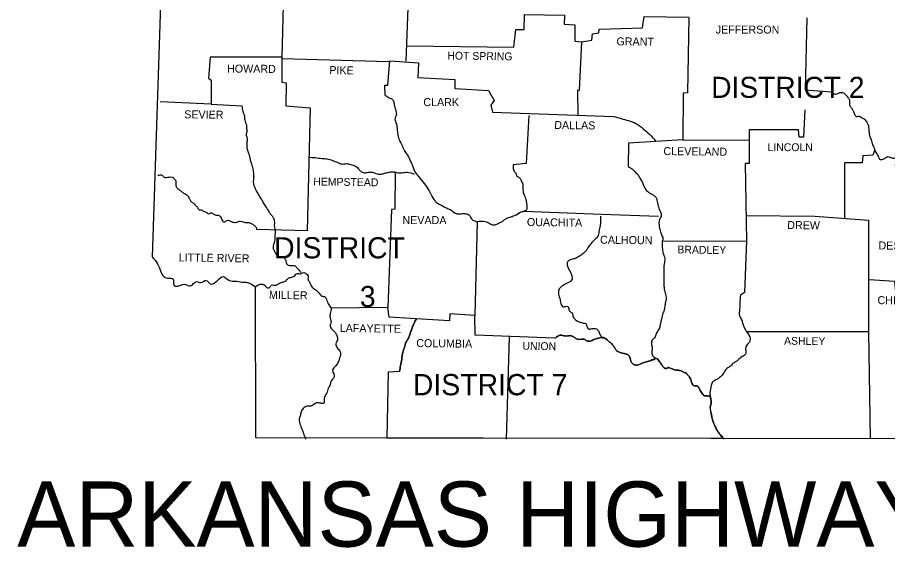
# Model space of a CAD drawing. Extents: x 185 to 5012, y 113 to 2127.
# Drawn here: x 4271.6 to 4728.7, y 1375.6 to 1654.2 of the extents above; entities that cross this region are included whole.
import ezdxf

# ---------------------------------------------------------------- set-up
doc = ezdxf.new("R2010")
doc.units = 0
for name, color, linetype in [('1', 7, 'Continuous'), ('2', 7, 'Continuous'), ('3', 7, 'Continuous'), ('S_MISC_BOUNDARY', 7, 'Continuous')]:
    doc.layers.add(name, color=color, linetype=linetype)

msp = doc.modelspace()

# ---------------------------------------------------------------- linework, layer by layer
at = {"layer": '1'}
for points in [[(4330.91, 1956.42), (4351.16, 1793.81), (4342.35, 1528.37)], [(4477.96, 1692.15), (4475.71, 1631.2)], [(4411.63, 1681.39), (4410.55, 1633.25), (4372.88, 1633.35), (4372, 1622.19), (4373.37, 1621.22), (4373.27, 1608.69), (4346.56, 1609.87)], [(4476.4, 1639.32), (4532.36, 1638.53), (4533.44, 1647.83), (4537.84, 1647.83), (4537.94, 1655.66), (4559.07, 1655.36), (4558.88, 1650.67), (4564.35, 1650.27), (4564.35, 1641.66), (4567.88, 1641.37)], [(4567.88, 1641.37), (4573.36, 1642.15), (4573.75, 1645.48), (4576.98, 1646.07), (4577.17, 1648.02), (4599.97, 1648.71), (4600.85, 1654.68), (4624.23, 1654.29)], [(4624.23, 1654.09), (4623.65, 1614.56), (4621.4, 1614.47), (4621.1, 1589.91)], [(4686.26, 1653.99), (4685.48, 1616.13), (4699.08, 1615.05)], [(4567.88, 1641.37), (4566.7, 1615.74), (4565.82, 1616.03), (4565.92, 1602.72)], [(4410.55, 1633.25), (4410.55, 1620.24), (4412.7, 1619.85), (4412.51, 1607.71), (4425.42, 1606.74), (4423.86, 1542.06), (4397.24, 1542.75)], [(4410.74, 1632.57), (4466.71, 1631.1)], [(4464.85, 1613.19), (4464.66, 1618.57), (4466.22, 1618.67), (4467.2, 1631.29), (4482.27, 1630.32), (4481.88, 1622.59), (4501.35, 1621.51), (4501.44, 1616.81), (4519.05, 1615.74), (4522.09, 1610.45), (4520.23, 1608.11), (4521.11, 1604.49), (4584.9, 1602.14)], [(4373.27, 1608.69), (4389.51, 1607.71)], [(4685.19, 1605.66), (4684.6, 1591.28), (4682.35, 1591.28), (4681.96, 1595.09), (4655.93, 1595.09), (4655.93, 1589.61)], [(4540.29, 1602.63), (4538.82, 1577.48), (4532.07, 1576.7)], [(4607.01, 1589.03), (4592.53, 1588.15), (4592.44, 1575.92)], [(4621.1, 1589.91), (4606.82, 1589.03)], [(4621.1, 1589.91), (4655.74, 1589.71)], [(4655.93, 1589.71), (4656.03, 1577.48), (4653.98, 1577.38), (4654.56, 1536.78)], [(4722.07, 1584.53), (4720.9, 1581.88), (4715.71, 1581.4), (4715.42, 1577.87), (4706.13, 1577.87), (4706.03, 1548.62)], [(4470.04, 1572.98), (4469.84, 1553.51), (4468.08, 1553.31), (4466.12, 1501.75)], [(4537.84, 1552.34), (4578.35, 1550.87), (4608.38, 1549.69)], [(4654.27, 1550.09), (4690.57, 1549.79), (4718.75, 1547.64)], [(4513.18, 1546.86), (4511.91, 1497.55), (4498.7, 1498.43), (4498.61, 1494.81), (4480.99, 1495.88)], [(4718.75, 1547.64), (4718.75, 1489.13), (4719.53, 1432.87)], [(4610.34, 1536.68), (4654.56, 1536.78)], [(4654.56, 1536.78), (4653.59, 1509.58), (4651.43, 1508.21)], [(4719.24, 1516.43), (4732.35, 1515.65), (4732.93, 1509.97), (4744.77, 1510.36), (4745.26, 1515.16), (4747.51, 1515.16)], [(4396.46, 1512.61), (4396.66, 1433.46), (4755.24, 1432.87)], [(4480.99, 1495.88), (4466.81, 1496.67), (4466.12, 1501.75), (4436.48, 1501.46)], [(4553.89, 1485.61), (4512.11, 1487.17), (4511.91, 1497.06)], [(4529.91, 1486.29), (4528.35, 1432.58)], [(4655.15, 1489.23), (4718.75, 1489.23)], [(4472.38, 1468.19), (4466.32, 1467.8), (4465.63, 1433.36)]]:
    msp.add_lwpolyline(points, dxfattribs=at)
for points in [[(4699.08, 1615.05), (4700.55, 1614.07), (4702.6, 1614.17), (4703.97, 1614.76), (4705.05, 1614.66), (4706.52, 1613.78), (4707.5, 1612.61), (4708.18, 1611.73), (4708.67, 1610.36), (4708.67, 1609.08), (4709.16, 1607.32), (4709.75, 1606.64), (4710.53, 1605.37), (4711.02, 1604.19), (4711.31, 1603.41), (4712.39, 1602.14), (4713.37, 1602.24), (4714.25, 1602.14), (4715.42, 1601.45), (4717.18, 1600.08), (4717.48, 1599.69), (4718.65, 1597.15), (4718.85, 1595.58), (4719.04, 1593.53), (4719.43, 1591.57), (4720.22, 1589.42), (4720.61, 1587.95), (4721.49, 1585.9), (4722.07, 1584.53), (4722.86, 1582.76), (4724.03, 1580.81), (4724.52, 1579.63), (4726.18, 1579.73), (4727.36, 1580.22), (4728.24, 1581), (4729.31, 1580.91), (4730.49, 1580.51), (4732.05, 1580.22), (4733.03, 1580.81), (4733.52, 1581.2), (4733.62, 1582.08), (4734.5, 1582.57), (4735.48, 1581.88), (4736.55, 1580.32), (4736.55, 1579.34), (4736.16, 1578.75), (4734.89, 1577.97), (4733.13, 1577.38), (4732.64, 1576.7), (4734.3, 1575.92), (4736.95, 1575.72), (4737.63, 1576.31), (4739.39, 1575.82), (4740.08, 1576.31), (4742.42, 1576.21), (4743.5, 1576.99), (4745.65, 1576.89), (4746.34, 1576.41), (4746.34, 1575.52), (4748.1, 1575.13), (4749.37, 1575.43), (4751.03, 1574.94), (4752.5, 1574.15), (4753.29, 1573.08), (4754.26, 1571.9), (4755.14, 1572.2), (4755.83, 1573.08), (4757.3, 1574.64), (4757.3, 1575.62), (4757.69, 1576.31), (4758.18, 1577.29)], [(4464.85, 1613.19), (4466.42, 1612.21), (4468.28, 1611.33), (4469.25, 1609.87), (4469.65, 1607.62), (4470.33, 1605.17), (4470.53, 1602.63), (4469.94, 1601.26), (4470.72, 1598.13), (4471.01, 1595.97), (4471.31, 1593.43), (4472.09, 1590.01), (4473.36, 1587.66), (4474.54, 1584.82), (4476.49, 1581.79), (4478.16, 1578.46), (4478.94, 1576.7), (4480.41, 1573.08), (4482.27, 1570.63), (4485.2, 1566.91), (4487.84, 1563.1), (4489.31, 1560.26), (4491.56, 1557.13), (4494.11, 1555.57), (4497.33, 1553.9), (4499.39, 1552.92), (4501.74, 1551.26), (4504.77, 1551.06), (4507.02, 1551.06), (4509.07, 1550.18), (4510.05, 1548.42), (4511.81, 1547.25), (4513.18, 1546.86)], [(4389.51, 1607.71), (4390, 1604.78), (4390.88, 1602.24), (4390.98, 1600.28), (4391.86, 1597.34), (4391.86, 1596.27), (4392.16, 1594.11), (4391.76, 1592.94), (4392.25, 1590.59), (4392.16, 1588.83), (4392.16, 1587.36), (4392.25, 1584.92), (4393.04, 1582.76), (4393.82, 1579.54), (4394.31, 1577.87), (4395.09, 1575.33), (4395.58, 1572.2), (4395.68, 1569.85), (4395.48, 1567.7), (4396.07, 1565.25), (4397.15, 1562.81), (4398.51, 1560.46), (4400.18, 1557.82), (4401.35, 1555.76), (4402.82, 1553.51), (4403.99, 1551.65), (4405.76, 1549.3), (4406.54, 1547.35), (4406.54, 1544.61), (4406.93, 1542.06), (4406.83, 1539.23), (4406.64, 1536.68), (4405.95, 1533.16), (4406.44, 1531.5), (4408.3, 1529.05), (4409.47, 1528.37), (4411.53, 1527.97), (4412.51, 1526.6), (4413.09, 1524.55), (4415.15, 1523.86), (4417.4, 1523.67), (4418.47, 1522.49), (4419.94, 1520.93), (4420.43, 1520.15)], [(4584.9, 1602.14), (4592.53, 1599.98), (4596.45, 1598.52), (4600.36, 1595.68), (4603.59, 1592.84), (4606.82, 1589.22)], [(4425.23, 1580.71), (4428.94, 1580.42), (4432.37, 1580.03), (4435.01, 1579.73), (4437.75, 1578.75), (4440.2, 1577.87), (4441.76, 1577.19), (4444.4, 1577.38), (4446.65, 1576.89), (4449.2, 1576.01), (4451.06, 1574.35), (4452.23, 1573.08), (4454.48, 1572.59), (4456.34, 1572.88), (4458.59, 1572.69), (4461.13, 1571.9), (4463.19, 1572), (4464.85, 1572.39), (4466.81, 1572.88), (4469.25, 1573.08), (4471.11, 1572.69), (4473.56, 1572.59), (4476.4, 1572.88), (4479.92, 1571.9)], [(4532.07, 1576.7), (4532.07, 1574.84), (4532.75, 1573.08), (4533.44, 1572.3), (4533.73, 1571.02), (4534.61, 1570.44), (4535.88, 1569.26), (4536.57, 1567.6), (4537.06, 1566.52), (4537.06, 1565.15), (4537.16, 1563.78), (4537.35, 1562.12), (4538.52, 1559.19), (4538.82, 1558.01), (4539.01, 1557.03), (4539.11, 1555.37), (4539.11, 1553.41), (4537.84, 1552.34)], [(4592.44, 1575.92), (4594.69, 1574.45), (4596.54, 1572.49), (4597.91, 1571.02), (4598.79, 1569.36), (4599.97, 1567.4), (4601.63, 1563.69), (4603.1, 1562.41), (4605.15, 1561.14), (4606.43, 1560.26), (4607.7, 1557.42), (4608.29, 1554.59), (4609.36, 1552.04), (4609.85, 1550.09), (4608.97, 1548.13), (4608.77, 1544.22), (4609.36, 1541.57), (4610.14, 1539.62), (4610.63, 1537.37), (4610.34, 1536.68)], [(4345.39, 1571.22), (4347.54, 1571.32), (4349.01, 1570.05), (4349.89, 1570.14), (4351.45, 1570.34), (4352.92, 1570.24), (4354, 1569.36), (4354.88, 1567.8), (4354.78, 1566.33), (4354.88, 1565.74), (4355.56, 1564.47), (4356.74, 1563.49), (4358.01, 1562.51), (4359.18, 1561.73), (4361.14, 1560.46), (4361.34, 1560.07), (4362.12, 1558.5), (4363.1, 1557.23), (4364.27, 1556.45), (4365.54, 1555.08), (4366.13, 1554.49), (4367.11, 1553.12), (4368.18, 1553.02), (4369.65, 1552.14), (4370.73, 1551.85), (4371.9, 1551.06), (4373.08, 1551.46), (4374.54, 1550.87), (4376.5, 1550.28), (4377.58, 1550.09), (4378.85, 1548.23), (4380.12, 1546.66), (4381.69, 1547.54), (4384.62, 1546.66), (4386.48, 1546.56), (4388.14, 1547.05), (4389.42, 1546.96), (4391.76, 1546.37), (4393.23, 1546.37), (4394.8, 1545.78), (4396.26, 1544.61), (4397.24, 1543.34), (4397.24, 1542.75)], [(4535.98, 1551.95), (4533.44, 1550.28), (4531.48, 1549.5), (4530.01, 1549.01), (4528.64, 1548.62), (4526.88, 1547.44), (4525.51, 1546.47), (4523.65, 1545.59), (4521.89, 1545), (4519.74, 1545.68), (4518.57, 1546.37), (4517.29, 1546.86), (4513.18, 1546.86)], [(4533.44, 1550.28), (4535.98, 1551.95), (4537.84, 1552.34)], [(4577.95, 1549.69), (4577.76, 1544.8), (4577.07, 1541.77), (4576.39, 1539.03), (4574.92, 1537.46), (4573.36, 1535.9), (4571.89, 1534.14), (4570.62, 1531.99), (4569.34, 1530.62), (4567.68, 1529.25), (4566.02, 1528.27), (4564.16, 1527.39), (4562.1, 1526.9), (4560.64, 1525.82), (4560.54, 1523.47), (4562.2, 1520.15), (4562.79, 1518.58), (4562.99, 1516.72), (4562.3, 1515.65), (4560.73, 1514.77), (4558.88, 1513.69), (4557.21, 1512.71), (4556.04, 1511.05), (4555.84, 1508.8), (4556.63, 1506.16), (4556.92, 1504.59), (4558.19, 1502.14), (4559.17, 1502.24), (4560.93, 1502.14), (4561.13, 1501.65), (4561.22, 1501.17), (4561.62, 1499.89), (4563.08, 1498.82), (4563.28, 1497.84), (4564.16, 1495.98), (4565.63, 1494.71), (4566.7, 1494.32), (4568.95, 1493.63), (4570.13, 1493.34), (4571.4, 1490.5), (4572.96, 1490.6), (4574.14, 1490.79), (4576.1, 1490.31), (4576.98, 1489.13), (4577.86, 1487.17), (4579.03, 1485.8), (4579.81, 1485.8)], [(4610.34, 1536.68), (4610.73, 1530.62), (4611.61, 1527.68), (4611.32, 1524.55), (4611.22, 1521.52), (4611.22, 1518.78), (4611.22, 1516.14), (4611.22, 1513.4), (4611.42, 1511.44), (4612.1, 1508.6), (4612.39, 1505.96), (4611.81, 1503.42), (4611.51, 1501.07), (4610.73, 1498.72), (4610.05, 1496.08), (4609.26, 1492.65), (4608.58, 1490.4), (4607.21, 1488.06), (4606.33, 1485.9), (4604.96, 1484.53), (4604.76, 1482.18), (4605.06, 1480.03), (4604.86, 1478.08), (4605.55, 1476.22), (4607.31, 1474.94)], [(4342.35, 1528.37), (4345.19, 1524.65), (4346.37, 1522.01), (4348.03, 1518.58), (4350.48, 1517.21), (4353.31, 1516.72), (4353.9, 1513.4), (4356.83, 1513.3), (4359.18, 1513.98), (4362.41, 1513.1), (4365.84, 1515.45), (4367.79, 1514.86), (4370.63, 1516.04), (4372.78, 1514.28), (4376.5, 1515.84), (4379.83, 1517.99), (4382.96, 1515.94), (4385.99, 1515.65), (4389.61, 1515.16), (4392.45, 1514.96), (4394.99, 1513.69), (4396.85, 1512.42), (4396.46, 1512.61)], [(4396.46, 1512.61), (4399.88, 1514.08), (4401.35, 1513.59), (4402.62, 1512.32), (4404.09, 1512.32), (4404.87, 1513.49), (4406.34, 1513.59), (4407.52, 1513.49), (4408.79, 1514.28), (4409.86, 1514.77), (4411.33, 1515.25), (4412.41, 1515.65), (4413.39, 1516.72), (4415.15, 1517.6), (4417.2, 1518.29), (4417.79, 1519.27), (4418.77, 1519.66), (4420.72, 1519.56), (4422, 1520.15), (4423.07, 1519.66), (4424.05, 1518.97), (4424.25, 1516.43), (4425.03, 1515.06), (4426.2, 1512.61), (4427.87, 1511.34), (4429.43, 1510.07), (4430.02, 1509.29), (4431.68, 1507.82), (4433.15, 1507.33), (4433.84, 1506.25), (4434.91, 1503.71), (4436.48, 1501.46)], [(4651.43, 1508.21), (4651.14, 1505.18), (4651.04, 1502.34), (4650.85, 1499.6), (4650.85, 1497.55), (4652.02, 1495.3), (4652.7, 1493.14), (4653.39, 1491.28), (4654.76, 1488.84), (4656.03, 1486.98), (4656.42, 1484.34), (4655.64, 1482.97), (4654.17, 1480.91), (4654.07, 1477.19), (4652.31, 1476.02), (4650.06, 1474.06), (4648.79, 1473.18), (4647.42, 1472.3), (4645.95, 1470.74), (4643.8, 1469.27), (4642.24, 1466.82), (4640.47, 1464.96), (4639.01, 1463.99), (4636.95, 1462.71), (4636.07, 1460.76), (4635.39, 1457.14), (4635.68, 1454.5), (4636.07, 1452.15), (4635.58, 1449.21), (4636.07, 1445.98), (4636.56, 1443.44), (4637.34, 1441.19), (4638.42, 1438.65), (4639.79, 1436.3), (4642.73, 1432.68)], [(4436.48, 1501.46), (4435.89, 1498.62), (4435.79, 1496.37), (4436.28, 1493.73), (4435.79, 1492.46), (4436.57, 1490.6), (4438.04, 1489.13), (4439.12, 1487.57), (4439.8, 1485.32), (4438.92, 1482.77), (4439.9, 1480.13), (4440.78, 1479.15), (4441.27, 1477.59), (4440.59, 1474.55), (4439.71, 1472.3), (4437.75, 1470.05), (4437.16, 1468.98), (4437.46, 1467.51), (4437.94, 1465.16), (4437.46, 1464.48), (4436.18, 1462.81), (4435.79, 1460.95), (4434.91, 1459.39), (4433.93, 1456.55), (4432.66, 1454.2), (4432.47, 1451.56), (4430.51, 1451.56), (4428.26, 1451.56), (4426.2, 1450.09), (4424.34, 1450), (4422.09, 1449.11), (4420.72, 1447.26), (4420.24, 1445.2), (4419.65, 1443.24), (4420.24, 1439.92), (4421.12, 1437.57), (4421.8, 1435.71), (4422.98, 1432.68)], [(4472.38, 1468.19), (4472.87, 1471.32), (4473.36, 1473.77), (4473.66, 1476.12), (4474.24, 1478.76), (4475.12, 1481.6), (4475.91, 1483.95), (4476.98, 1485.61), (4477.67, 1487.57), (4478.55, 1489.91), (4479.43, 1492.36), (4480.99, 1495.49)], [(4553.89, 1485.61), (4555.45, 1486.69), (4556.92, 1487.27), (4558.39, 1486.98), (4559.95, 1486.78), (4561.32, 1486.98), (4563.08, 1486.69), (4564.55, 1485.8), (4566.21, 1485.12), (4567.88, 1485.12), (4569.34, 1485.12), (4570.62, 1484.24), (4572.96, 1484.34), (4574.92, 1485.12), (4576.88, 1485.71), (4579.52, 1486), (4581.87, 1484.34), (4583.53, 1482.97), (4584.9, 1481.4), (4585.88, 1479.64), (4586.96, 1478.66), (4588.72, 1477.98), (4590.09, 1477.68), (4591.75, 1477.19), (4592.63, 1476.8), (4593.41, 1474.94), (4594.69, 1472.4), (4597.13, 1471.52), (4600.16, 1472.69), (4602.61, 1473.38), (4604.37, 1473.97), (4605.45, 1474.36), (4606.43, 1474.46), (4606.13, 1474.65), (4607.31, 1474.94), (4608.38, 1474.16), (4609.07, 1473.09), (4610.24, 1471.52), (4611.32, 1470.15), (4612.39, 1469.66), (4613.47, 1470.25), (4614.94, 1469.76), (4616.21, 1469.27), (4617.68, 1468.88), (4618.95, 1468.78), (4620.61, 1468.39), (4621.89, 1467.7), (4623.06, 1467.02), (4624.23, 1465.75), (4625.41, 1463.79), (4625.8, 1462.23), (4627.17, 1460.66), (4628.44, 1460.66), (4630.3, 1458.12), (4630.98, 1457.14), (4632.45, 1455.38), (4633.53, 1455.38), (4635.58, 1454.98)]]:
    msp.add_spline(points, degree=3, dxfattribs=at)
at = {"layer": 'S_MISC_BOUNDARY'}
for p, q in [((4480.99, 1495.88), (4480.99, 1495.49)), ((4465.63, 1433.35), (4642.37, 1433.06))]:
    msp.add_line(p, q, dxfattribs=at)
for points in [[(4511.9, 1497.55), (4498.7, 1498.43), (4498.61, 1494.81), (4480.99, 1495.88)], [(4553.89, 1485.61), (4512.11, 1487.17), (4511.9, 1497.55)], [(4472.38, 1468.19), (4466.32, 1467.8), (4465.63, 1433.35)]]:
    msp.add_lwpolyline(points, dxfattribs=at)
for points in [[(4480.99, 1495.49), (4479.43, 1492.36), (4478.55, 1489.91), (4477.67, 1487.57), (4476.98, 1485.61), (4475.91, 1483.95), (4475.12, 1481.6), (4474.24, 1478.76), (4473.66, 1476.12), (4473.36, 1473.77), (4472.87, 1471.32), (4472.38, 1468.19)], [(4596.16, 1471.51), (4594.69, 1472.4), (4593.41, 1474.94), (4592.63, 1476.8), (4591.75, 1477.19), (4590.09, 1477.68), (4588.72, 1477.98), (4586.96, 1478.66), (4585.88, 1479.64), (4584.9, 1481.4), (4583.53, 1482.97), (4581.87, 1484.34), (4579.52, 1486), (4576.88, 1485.71), (4574.92, 1485.12), (4572.96, 1484.34), (4570.62, 1484.24), (4569.34, 1485.12), (4567.88, 1485.12), (4566.21, 1485.12), (4564.55, 1485.8), (4563.08, 1486.69), (4561.32, 1486.98), (4559.95, 1486.78), (4558.39, 1486.98), (4556.92, 1487.27), (4555.45, 1486.69), (4553.89, 1485.61)], [(4635.58, 1454.98), (4633.53, 1455.38), (4632.45, 1455.38), (4630.98, 1457.14), (4630.3, 1458.12), (4628.44, 1460.66), (4627.17, 1460.66), (4625.8, 1462.23), (4625.41, 1463.79), (4624.23, 1465.75), (4623.06, 1467.02), (4621.89, 1467.7), (4620.61, 1468.39), (4618.95, 1468.78), (4617.68, 1468.88), (4616.21, 1469.27), (4614.94, 1469.76), (4613.47, 1470.25), (4612.39, 1469.66), (4611.32, 1470.15), (4610.24, 1471.52), (4609.07, 1473.09), (4608.38, 1474.16), (4607.31, 1474.94), (4606.13, 1474.65), (4606.43, 1474.46), (4605.45, 1474.36), (4604.37, 1473.97), (4602.61, 1473.38), (4600.16, 1472.69), (4597.13, 1471.52), (4596.16, 1471.51)], [(4642.37, 1433.06), (4641.02, 1434.63), (4639.79, 1436.3), (4639.41, 1436.87), (4639.06, 1437.45), (4638.42, 1438.65), (4637.86, 1439.91), (4637.6, 1440.55), (4637.34, 1441.19), (4636.92, 1442.3), (4636.56, 1443.44), (4636.42, 1444.07), (4636.29, 1444.71), (4636.07, 1445.98), (4635.93, 1446.79), (4635.8, 1447.6), (4635.69, 1448.4), (4635.58, 1449.21), (4635.63, 1449.95), (4635.83, 1450.68), (4636.03, 1451.41), (4636.07, 1452.15), (4635.91, 1453.17), (4635.58, 1454.98)]]:
    msp.add_spline(points, degree=3, dxfattribs=at)

# ---------------------------------------------------------------- texts
at = {"layer": '2'}
for s, height, p in [('JEFFERSON', 4.207, (4638.42, 1645.68)), ('CLARK', 4.207, (4484.83, 1607.59)), ('LINCOLN', 4.109, (4665.62, 1583.94)), ('NEVADA', 4.207, (4473.85, 1545.59)), ('CHICOT', 4.207, (4723.44, 1503.51)), ('ARKANSAS HIGHWAY DISTRICT 7', 34.244, (4271.47, 1376.13))]:
    msp.add_text(s, height=height, dxfattribs=at).set_placement(p)
for s, height, rotation, p in [('GRANT', 4.207, 359.4032, (4586.27, 1639.51)), ('HOT SPRING', 4.109, 359.2216, (4497.43, 1632.08)), ('HOWARD', 4.207, 359.5145, (4381.69, 1625.23)), ('PIKE', 4.206, 359.0452, (4435.4, 1624.44)), ('SEVIER', 4.207, 359.4271, (4359.18, 1601.16)), ('DALLAS', 4.206, 359.2462, (4553.59, 1595.58)), ('CLEVELAND', 4.207, 359.3377, (4610.93, 1581.88)), ('HEMPSTEAD', 4.108, 359.1885, (4426.99, 1565.94)), ('OUACHITA', 4.207, 359.2043, (4539.21, 1544.61)), ('DREW', 4.206, 359.2258, (4675.99, 1543.04)), ('CALHOUN', 4.207, 359.3634, (4577.66, 1535.31)), ('DESHA', 4.206, 359.3704, (4723.93, 1532.28)), ('BRADLEY', 4.108, 359.1449, (4618.27, 1530.22)), ('LITTLE RIVER', 4.2073, 359.1697, (4356.25, 1526.02)), ('MILLER', 4.206, 359.1319, (4403.7, 1506.35)), ('LAFAYETTE', 4.206, 359.1839, (4440.88, 1488.94)), ('ASHLEY', 4.109, 359.2361, (4674.33, 1482.28)), ('COLUMBIA', 4.206, 359.2125, (4481.09, 1481.01)), ('UNION', 4.109, 358.9584, (4536.86, 1479.64))]:
    msp.add_text(s, height=height, rotation=rotation, dxfattribs=at).set_placement(p)
at = {"layer": '3'}
for s, height, p in [('DISTRICT 2', 11.056, (4636.07, 1611.92)), ('DISTRICT', 11.154, (4406.39, 1527.57)), ('3', 11.06, (4451.5, 1502.04)), ('DISTRICT 7', 11.154, (4479.33, 1455.67))]:
    msp.add_text(s, height=height, dxfattribs=at).set_placement(p)

doc.saveas('drawing.dxf')
